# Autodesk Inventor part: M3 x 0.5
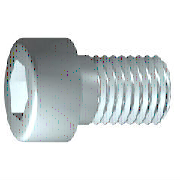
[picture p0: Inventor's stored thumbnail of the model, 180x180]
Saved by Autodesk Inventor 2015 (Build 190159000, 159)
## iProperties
IsCustomPart: 0
Created: 2015-10
Part Number: M3 x 0.5
Material: Steel, Mild
Description: 6각머리 태핑 나사
Document SubType Name: Modeling
Standard: KS B 1003
Designer: mdu
Standards Organization: KS
Language: ko-KR
Size Designation: M 3 x 12
Categories: <MemberInstance><Categories><Category DisplayName="조임쇠" InternalName="e4da775c-781d-43d5-af7c-5136215cf5a6" Mnemonic="FSTN"><Category DisplayName="볼트" InternalN
Density: 1 g/cm^3
Appearance: Steel
Author: mdu
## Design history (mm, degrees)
revolve "본체" stored, may be unused: angle "d10" = 90 deg
sketch "스케치2"
  geometry: L1 (0, -3.85)-(0, 3.85) reference; L2 (-3.85, 0)-(3.85, 0) reference; L3 (1.443, 0)-(0.722, -1.25); L4 (0.722, -1.25)-(-0.722, -1.25); L5 (-0.722, -1.25)-(-1.443, 0); L6 (-1.443, 0)-(-0.722, 1.25); L7 (-0.722, 1.25)-(0.722, 1.25); L8 (0.722, 1.25)-(1.443, 0); 2 further points
  constraints: 12 end point, 1 coincident, 1 horizontal alignment, 1 point on line, 12 other
extrude "슬롯" join sketch "스케치2" stored distance "d11" = 10; taper "d12" = 0 deg
workplane "Work Plane1"
fillet "Fillet2" dims "d30" = 0.1 (= R)
body "Solid1"
fillet "모깎기1" dims "d17" = 0.3 (= RR)
feature "스레드" dims "d13" = 10.75 (= GEL), "d14" = 0
chamfer "모따기1" distance "d15" = 0.30673 (= -0.5 x SPD + 0.5 x GD); stored, may be unused: second distance "d16" = 0.30673 (= GUL), angle "d27" = 45 deg
sketch "스케치1"
  geometry: L1 (-0.867, 0)-(12, 0); L2 (12, 0)-(12, 1.5); L3 (12, 1.5)-(1.25, 1.5); L4 (1.25, 1.5)-(0.943, 1.5); L5 (0.943, 1.5)-(0, 1.5); L6 (0, 1.5)-(0, 2.75); L7 (0, 2.75)-(-3, 2.75); L8 (-3, 2.75)-(-3, 1.443); L9 (-3, 1.443)-(-1.7, 1.443); L10 (-1.7, 1.443)-(-0.867, 0); L11 (-6, 0)-(15, 0) reference; L12 (0, -0.55)-(0, 3.3) reference; L13 (1.25, 1.5)-(0, 1.5)
  constraints: 22 end point, 6 parallel, 2 collinear, 2 perpendicular, 1 horizontal, 1 point on line
  dimensions: "d1" = 10.75 distance from line of L3.end L2 (= GEL); "d2" = 0.30683 distance of L4.end L3.end (computed from GAL); "d3" = 3 distance between parallel lines of L8 L6 (= KOH); "d4" = 1.3 distance of L8.end L9.end (= INTI); "d5" = 60 deg angle of L10 L1; "d6" = 3 diameter of L3 L1 (= GD); "d7" = 3 diameter of L5 L1 (= BDM); "d8" = 2.88675 diameter of L9 L1 (= 1.1547 x SW); "d9" = 5.5 diameter of L7 L1 (= KOD); "d26" = 12 distance between parallel lines of L12 L2 (= NLG)
other parameters: "GD" = 3 (= NND) [user parameter; used in 2 equation terms], "NLG" = 12 [user parameter; used in 1 equation term], "GEL" = 10.75 [user parameter; used in 2 equation terms], "KOD" = 5.5 [user parameter; used in 1 equation term], "KOH" = 3 [user parameter; used in 1 equation term], "INTI" = 1.3 [user parameter; used in 1 equation term], "GAL" = 0.30673 (= 0.61345 x PTC) [user parameter; used in 1 equation term], "GUL" = 0.30673 (= 0.61345 x PTC) [user parameter; used in 1 equation term], "BDM" = 3 (= NND) [user parameter; used in 1 equation term], "SW" = 2.5 [user parameter; used in 2 equation terms], "RR" = 0.3 [user parameter; used in 1 equation term], "SPD" = 2.38655 (= NND - 1.2269 x PTC) [user parameter; used in 1 equation term], "d19" = 0, "d28" = 0, "d29" = 0, "R" = 0.1 [user parameter; used in 1 equation term], "PHH" = 0.1 [user parameter], "GD1" = 2.38655 (= THREADDIA - 1.2269 x PTC) [user parameter], "THREADDIA" = 3 [user parameter; used in 1 equation term], "FAWI" = 45 deg [user parameter], "PTC" = 0.5 [user parameter; used in 5 equation terms], "NND" = 3 [user parameter; used in 3 equation terms], "TOA" = 30 deg [user parameter], "E0" = 2.8875 (= 1.155 x SW) [user parameter]
